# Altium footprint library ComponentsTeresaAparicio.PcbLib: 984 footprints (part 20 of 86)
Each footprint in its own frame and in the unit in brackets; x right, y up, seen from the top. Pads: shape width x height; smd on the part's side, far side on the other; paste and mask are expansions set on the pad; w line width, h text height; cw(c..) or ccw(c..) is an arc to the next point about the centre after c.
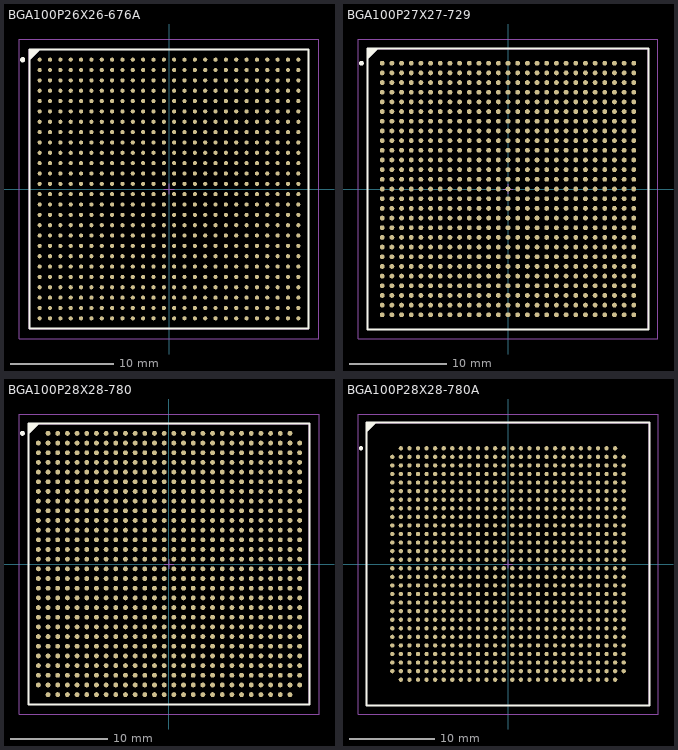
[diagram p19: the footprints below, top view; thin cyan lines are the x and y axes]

## BGA100P26X26-676A [mm] "BGA, 676-Leads, Body 27x27mm, Pitch 1mm"
height 1.6
pads (676):
  round 0.4 smd: A1(-12.5,12.5) A2(-11.5,12.5) A3(-10.5,12.5) A4(-9.5,12.5) A5(-8.5,12.5) A6(-7.5,12.5) A7(-6.5,12.5) A8(-5.5,12.5) A9(-4.5,12.5) A10(-3.5,12.5) A11(-2.5,12.5) A12(-1.5,12.5) A13(-0.5,12.5) A14(0.5,12.5) A15(1.5,12.5) A16(2.5,12.5) A17(3.5,12.5) A18(4.5,12.5) A19(5.5,12.5) A20(6.5,12.5) A21(7.5,12.5) A22(8.5,12.5) A23(9.5,12.5) A24(10.5,12.5) A25(11.5,12.5) A26(12.5,12.5) AA1(-12.5,-7.5) AA2(-11.5,-7.5) AA3(-10.5,-7.5) AA4(-9.5,-7.5) AA5(-8.5,-7.5) AA6(-7.5,-7.5) AA7(-6.5,-7.5) AA8(-5.5,-7.5) AA9(-4.5,-7.5) AA10(-3.5,-7.5) AA11(-2.5,-7.5) AA12(-1.5,-7.5) AA13(-0.5,-7.5) AA14(0.5,-7.5) AA15(1.5,-7.5) AA16(2.5,-7.5) AA17(3.5,-7.5) AA18(4.5,-7.5) AA19(5.5,-7.5) AA20(6.5,-7.5) AA21(7.5,-7.5) AA22(8.5,-7.5) AA23(9.5,-7.5) AA24(10.5,-7.5) AA25(11.5,-7.5) AA26(12.5,-7.5) AB1(-12.5,-8.5) AB2(-11.5,-8.5) AB3(-10.5,-8.5) AB4(-9.5,-8.5) AB5(-8.5,-8.5) AB6(-7.5,-8.5) AB7(-6.5,-8.5) AB8(-5.5,-8.5) AB9(-4.5,-8.5) AB10(-3.5,-8.5) AB11(-2.5,-8.5) AB12(-1.5,-8.5) AB13(-0.5,-8.5) AB14(0.5,-8.5) AB15(1.5,-8.5) AB16(2.5,-8.5) AB17(3.5,-8.5) AB18(4.5,-8.5) AB19(5.5,-8.5) AB20(6.5,-8.5) AB21(7.5,-8.5) AB22(8.5,-8.5) AB23(9.5,-8.5) AB24(10.5,-8.5) AB25(11.5,-8.5) AB26(12.5,-8.5) AC1(-12.5,-9.5) AC2(-11.5,-9.5) AC3(-10.5,-9.5) AC4(-9.5,-9.5) AC5(-8.5,-9.5) AC6(-7.5,-9.5) AC7(-6.5,-9.5) AC8(-5.5,-9.5) AC9(-4.5,-9.5) AC10(-3.5,-9.5) AC11(-2.5,-9.5) AC12(-1.5,-9.5) AC13(-0.5,-9.5) AC14(0.5,-9.5) AC15(1.5,-9.5) AC16(2.5,-9.5) AC17(3.5,-9.5) AC18(4.5,-9.5) AC19(5.5,-9.5) AC20(6.5,-9.5) AC21(7.5,-9.5) AC22(8.5,-9.5) AC23(9.5,-9.5) AC24(10.5,-9.5) AC25(11.5,-9.5) AC26(12.5,-9.5) AD1(-12.5,-10.5) AD2(-11.5,-10.5) AD3(-10.5,-10.5) AD4(-9.5,-10.5) AD5(-8.5,-10.5) AD6(-7.5,-10.5) AD7(-6.5,-10.5) AD8(-5.5,-10.5) AD9(-4.5,-10.5) AD10(-3.5,-10.5) AD11(-2.5,-10.5) AD12(-1.5,-10.5) AD13(-0.5,-10.5) AD14(0.5,-10.5) AD15(1.5,-10.5) AD16(2.5,-10.5) AD17(3.5,-10.5) AD18(4.5,-10.5) AD19(5.5,-10.5) AD20(6.5,-10.5) AD21(7.5,-10.5) AD22(8.5,-10.5) AD23(9.5,-10.5) AD24(10.5,-10.5) AD25(11.5,-10.5) AD26(12.5,-10.5) AE1(-12.5,-11.5) AE2(-11.5,-11.5) AE3(-10.5,-11.5) AE4(-9.5,-11.5) AE5(-8.5,-11.5) AE6(-7.5,-11.5) AE7(-6.5,-11.5) AE8(-5.5,-11.5) AE9(-4.5,-11.5) AE10(-3.5,-11.5) AE11(-2.5,-11.5) AE12(-1.5,-11.5) AE13(-0.5,-11.5) AE14(0.5,-11.5) AE15(1.5,-11.5) AE16(2.5,-11.5) AE17(3.5,-11.5) AE18(4.5,-11.5) AE19(5.5,-11.5) AE20(6.5,-11.5) AE21(7.5,-11.5) AE22(8.5,-11.5) AE23(9.5,-11.5) AE24(10.5,-11.5) AE25(11.5,-11.5) AE26(12.5,-11.5) AF1(-12.5,-12.5) AF2(-11.5,-12.5) AF3(-10.5,-12.5) AF4(-9.5,-12.5) AF5(-8.5,-12.5) AF6(-7.5,-12.5) AF7(-6.5,-12.5) AF8(-5.5,-12.5) AF9(-4.5,-12.5) AF10(-3.5,-12.5) AF11(-2.5,-12.5) AF12(-1.5,-12.5) AF13(-0.5,-12.5) AF14(0.5,-12.5) AF15(1.5,-12.5) AF16(2.5,-12.5) AF17(3.5,-12.5) AF18(4.5,-12.5) AF19(5.5,-12.5) AF20(6.5,-12.5) AF21(7.5,-12.5) AF22(8.5,-12.5) AF23(9.5,-12.5) AF24(10.5,-12.5) AF25(11.5,-12.5) AF26(12.5,-12.5) B1(-12.5,11.5) B2(-11.5,11.5) B3(-10.5,11.5) B4(-9.5,11.5) B5(-8.5,11.5) B6(-7.5,11.5) B7(-6.5,11.5) B8(-5.5,11.5) B9(-4.5,11.5) B10(-3.5,11.5) B11(-2.5,11.5) B12(-1.5,11.5) B13(-0.5,11.5) B14(0.5,11.5) B15(1.5,11.5) B16(2.5,11.5) B17(3.5,11.5) B18(4.5,11.5) B19(5.5,11.5) B20(6.5,11.5) B21(7.5,11.5) B22(8.5,11.5) B23(9.5,11.5) B24(10.5,11.5) B25(11.5,11.5) B26(12.5,11.5) C1(-12.5,10.5) C2(-11.5,10.5) C3(-10.5,10.5) C4(-9.5,10.5) C5(-8.5,10.5) C6(-7.5,10.5) C7(-6.5,10.5) C8(-5.5,10.5) C9(-4.5,10.5) C10(-3.5,10.5) C11(-2.5,10.5) C12(-1.5,10.5) C13(-0.5,10.5) C14(0.5,10.5) C15(1.5,10.5) C16(2.5,10.5) C17(3.5,10.5) C18(4.5,10.5) C19(5.5,10.5) C20(6.5,10.5) C21(7.5,10.5) C22(8.5,10.5) C23(9.5,10.5) C24(10.5,10.5) C25(11.5,10.5) C26(12.5,10.5) D1(-12.5,9.5) D2(-11.5,9.5) D3(-10.5,9.5) D4(-9.5,9.5) D5(-8.5,9.5) D6(-7.5,9.5) D7(-6.5,9.5) D8(-5.5,9.5) D9(-4.5,9.5) D10(-3.5,9.5) D11(-2.5,9.5) D12(-1.5,9.5) D13(-0.5,9.5) D14(0.5,9.5) D15(1.5,9.5) D16(2.5,9.5) D17(3.5,9.5) D18(4.5,9.5) D19(5.5,9.5) D20(6.5,9.5) D21(7.5,9.5) D22(8.5,9.5) D23(9.5,9.5) D24(10.5,9.5) D25(11.5,9.5) D26(12.5,9.5) E1(-12.5,8.5) E2(-11.5,8.5) E3(-10.5,8.5) E4(-9.5,8.5) E5(-8.5,8.5) E6(-7.5,8.5) E7(-6.5,8.5) E8(-5.5,8.5) E9(-4.5,8.5) E10(-3.5,8.5) E11(-2.5,8.5) E12(-1.5,8.5) E13(-0.5,8.5) E14(0.5,8.5) E15(1.5,8.5) E16(2.5,8.5) E17(3.5,8.5) E18(4.5,8.5) E19(5.5,8.5) E20(6.5,8.5) E21(7.5,8.5) E22(8.5,8.5) E23(9.5,8.5) E24(10.5,8.5) E25(11.5,8.5) E26(12.5,8.5) F1(-12.5,7.5) F2(-11.5,7.5) F3(-10.5,7.5) F4(-9.5,7.5) F5(-8.5,7.5) F6(-7.5,7.5) F7(-6.5,7.5) F8(-5.5,7.5) F9(-4.5,7.5) F10(-3.5,7.5) F11(-2.5,7.5) F12(-1.5,7.5) F13(-0.5,7.5) F14(0.5,7.5) F15(1.5,7.5) F16(2.5,7.5) F17(3.5,7.5) F18(4.5,7.5) F19(5.5,7.5) F20(6.5,7.5) F21(7.5,7.5) F22(8.5,7.5) F23(9.5,7.5) F24(10.5,7.5) F25(11.5,7.5) F26(12.5,7.5) G1(-12.5,6.5) G2(-11.5,6.5) G3(-10.5,6.5) G4(-9.5,6.5) G5(-8.5,6.5) G6(-7.5,6.5) G7(-6.5,6.5) G8(-5.5,6.5) G9(-4.5,6.5) G10(-3.5,6.5) G11(-2.5,6.5) G12(-1.5,6.5) G13(-0.5,6.5) G14(0.5,6.5) G15(1.5,6.5) G16(2.5,6.5) G17(3.5,6.5) G18(4.5,6.5) G19(5.5,6.5) G20(6.5,6.5) G21(7.5,6.5) G22(8.5,6.5) G23(9.5,6.5) G24(10.5,6.5) G25(11.5,6.5) G26(12.5,6.5) H1(-12.5,5.5) H2(-11.5,5.5) H3(-10.5,5.5) H4(-9.5,5.5) H5(-8.5,5.5) H6(-7.5,5.5) H7(-6.5,5.5) H8(-5.5,5.5) H9(-4.5,5.5) H10(-3.5,5.5) H11(-2.5,5.5) H12(-1.5,5.5) H13(-0.5,5.5) H14(0.5,5.5) H15(1.5,5.5) H16(2.5,5.5) H17(3.5,5.5) H18(4.5,5.5) H19(5.5,5.5) H20(6.5,5.5) H21(7.5,5.5) H22(8.5,5.5) H23(9.5,5.5) H24(10.5,5.5) H25(11.5,5.5) H26(12.5,5.5) J1(-12.5,4.5) J2(-11.5,4.5) J3(-10.5,4.5) J4(-9.5,4.5) J5(-8.5,4.5) J6(-7.5,4.5) J7(-6.5,4.5) J8(-5.5,4.5) J9(-4.5,4.5) J10(-3.5,4.5) J11(-2.5,4.5) J12(-1.5,4.5) J13(-0.5,4.5) J14(0.5,4.5) J15(1.5,4.5) J16(2.5,4.5) J17(3.5,4.5) J18(4.5,4.5) J19(5.5,4.5) J20(6.5,4.5) J21(7.5,4.5) J22(8.5,4.5) J23(9.5,4.5) J24(10.5,4.5) J25(11.5,4.5) J26(12.5,4.5) K1(-12.5,3.5) K2(-11.5,3.5) K3(-10.5,3.5) K4(-9.5,3.5) K5(-8.5,3.5) K6(-7.5,3.5) K7(-6.5,3.5) K8(-5.5,3.5) K9(-4.5,3.5) K10(-3.5,3.5) K11(-2.5,3.5) K12(-1.5,3.5) K13(-0.5,3.5) K14(0.5,3.5) K15(1.5,3.5) K16(2.5,3.5) K17(3.5,3.5) K18(4.5,3.5) K19(5.5,3.5) K20(6.5,3.5) K21(7.5,3.5) K22(8.5,3.5) K23(9.5,3.5) K24(10.5,3.5) K25(11.5,3.5) K26(12.5,3.5) L1(-12.5,2.5) L2(-11.5,2.5) L3(-10.5,2.5) L4(-9.5,2.5) L5(-8.5,2.5) L6(-7.5,2.5) L7(-6.5,2.5) L8(-5.5,2.5) L9(-4.5,2.5) L10(-3.5,2.5) L11(-2.5,2.5) L12(-1.5,2.5) L13(-0.5,2.5) L14(0.5,2.5) L15(1.5,2.5) L16(2.5,2.5) L17(3.5,2.5) L18(4.5,2.5) L19(5.5,2.5) L20(6.5,2.5) L21(7.5,2.5) L22(8.5,2.5) L23(9.5,2.5) L24(10.5,2.5) L25(11.5,2.5) L26(12.5,2.5) M1(-12.5,1.5) M2(-11.5,1.5) M3(-10.5,1.5) M4(-9.5,1.5) M5(-8.5,1.5) M6(-7.5,1.5) M7(-6.5,1.5) M8(-5.5,1.5) M9(-4.5,1.5) M10(-3.5,1.5) M11(-2.5,1.5) M12(-1.5,1.5) M13(-0.5,1.5) M14(0.5,1.5) M15(1.5,1.5) M16(2.5,1.5) M17(3.5,1.5) M18(4.5,1.5) M19(5.5,1.5) M20(6.5,1.5) M21(7.5,1.5) M22(8.5,1.5) M23(9.5,1.5) M24(10.5,1.5) M25(11.5,1.5) M26(12.5,1.5) N1(-12.5,0.5) N2(-11.5,0.5) N3(-10.5,0.5) N4(-9.5,0.5) N5(-8.5,0.5) N6(-7.5,0.5) N7(-6.5,0.5) N8(-5.5,0.5) N9(-4.5,0.5) N10(-3.5,0.5) N11(-2.5,0.5) N12(-1.5,0.5) N13(-0.5,0.5) N14(0.5,0.5) N15(1.5,0.5) N16(2.5,0.5) N17(3.5,0.5) N18(4.5,0.5) N19(5.5,0.5) N20(6.5,0.5) N21(7.5,0.5) N22(8.5,0.5) N23(9.5,0.5) N24(10.5,0.5) N25(11.5,0.5) N26(12.5,0.5) P1(-12.5,-0.5) P2(-11.5,-0.5) P3(-10.5,-0.5) P4(-9.5,-0.5) P5(-8.5,-0.5) P6(-7.5,-0.5) P7(-6.5,-0.5) P8(-5.5,-0.5) P9(-4.5,-0.5) P10(-3.5,-0.5) P11(-2.5,-0.5) P12(-1.5,-0.5) P13(-0.5,-0.5) P14(0.5,-0.5) P15(1.5,-0.5) P16(2.5,-0.5) P17(3.5,-0.5) P18(4.5,-0.5) P19(5.5,-0.5) P20(6.5,-0.5) P21(7.5,-0.5) P22(8.5,-0.5) P23(9.5,-0.5) P24(10.5,-0.5) P25(11.5,-0.5) P26(12.5,-0.5) R1(-12.5,-1.5) R2(-11.5,-1.5) R3(-10.5,-1.5) R4(-9.5,-1.5) R5(-8.5,-1.5) R6(-7.5,-1.5) R7(-6.5,-1.5) R8(-5.5,-1.5) R9(-4.5,-1.5) R10(-3.5,-1.5) R11(-2.5,-1.5) R12(-1.5,-1.5) R13(-0.5,-1.5) R14(0.5,-1.5) R15(1.5,-1.5) R16(2.5,-1.5) R17(3.5,-1.5) R18(4.5,-1.5) R19(5.5,-1.5) R20(6.5,-1.5) R21(7.5,-1.5) R22(8.5,-1.5) R23(9.5,-1.5) R24(10.5,-1.5) R25(11.5,-1.5) R26(12.5,-1.5) T1(-12.5,-2.5) T2(-11.5,-2.5) T3(-10.5,-2.5) T4(-9.5,-2.5) T5(-8.5,-2.5) T6(-7.5,-2.5) T7(-6.5,-2.5) T8(-5.5,-2.5) T9(-4.5,-2.5) T10(-3.5,-2.5) T11(-2.5,-2.5) T12(-1.5,-2.5) T13(-0.5,-2.5) T14(0.5,-2.5) T15(1.5,-2.5) T16(2.5,-2.5) T17(3.5,-2.5) T18(4.5,-2.5) T19(5.5,-2.5) T20(6.5,-2.5) T21(7.5,-2.5) T22(8.5,-2.5) T23(9.5,-2.5) T24(10.5,-2.5) T25(11.5,-2.5) T26(12.5,-2.5) U1(-12.5,-3.5) U2(-11.5,-3.5) U3(-10.5,-3.5) U4(-9.5,-3.5) U5(-8.5,-3.5) U6(-7.5,-3.5) U7(-6.5,-3.5) U8(-5.5,-3.5) U9(-4.5,-3.5) U10(-3.5,-3.5) U11(-2.5,-3.5) U12(-1.5,-3.5) U13(-0.5,-3.5) U14(0.5,-3.5) U15(1.5,-3.5) U16(2.5,-3.5) U17(3.5,-3.5) U18(4.5,-3.5) U19(5.5,-3.5) U20(6.5,-3.5) U21(7.5,-3.5) U22(8.5,-3.5) U23(9.5,-3.5) U24(10.5,-3.5) U25(11.5,-3.5) U26(12.5,-3.5) V1(-12.5,-4.5) V2(-11.5,-4.5) V3(-10.5,-4.5) V4(-9.5,-4.5) V5(-8.5,-4.5) V6(-7.5,-4.5) V7(-6.5,-4.5) V8(-5.5,-4.5) V9(-4.5,-4.5) V10(-3.5,-4.5) V11(-2.5,-4.5) V12(-1.5,-4.5) V13(-0.5,-4.5) V14(0.5,-4.5) V15(1.5,-4.5) V16(2.5,-4.5) V17(3.5,-4.5) V18(4.5,-4.5) V19(5.5,-4.5) V20(6.5,-4.5) V21(7.5,-4.5) V22(8.5,-4.5) V23(9.5,-4.5) V24(10.5,-4.5) V25(11.5,-4.5) V26(12.5,-4.5) W1(-12.5,-5.5) W2(-11.5,-5.5) W3(-10.5,-5.5) W4(-9.5,-5.5) W5(-8.5,-5.5) W6(-7.5,-5.5) W7(-6.5,-5.5) W8(-5.5,-5.5) W9(-4.5,-5.5) W10(-3.5,-5.5) W11(-2.5,-5.5) W12(-1.5,-5.5) W13(-0.5,-5.5) W14(0.5,-5.5) W15(1.5,-5.5) W16(2.5,-5.5) W17(3.5,-5.5) W18(4.5,-5.5) W19(5.5,-5.5) W20(6.5,-5.5) W21(7.5,-5.5) W22(8.5,-5.5) W23(9.5,-5.5) W24(10.5,-5.5) W25(11.5,-5.5) W26(12.5,-5.5) Y1(-12.5,-6.5) Y2(-11.5,-6.5) Y3(-10.5,-6.5) Y4(-9.5,-6.5) Y5(-8.5,-6.5) Y6(-7.5,-6.5) Y7(-6.5,-6.5) Y8(-5.5,-6.5) Y9(-4.5,-6.5) Y10(-3.5,-6.5) Y11(-2.5,-6.5) Y12(-1.5,-6.5) Y13(-0.5,-6.5) Y14(0.5,-6.5) Y15(1.5,-6.5) Y16(2.5,-6.5) Y17(3.5,-6.5) Y18(4.5,-6.5) Y19(5.5,-6.5) Y20(6.5,-6.5) Y21(7.5,-6.5) Y22(8.5,-6.5) Y23(9.5,-6.5) Y24(10.5,-6.5) Y25(11.5,-6.5) Y26(12.5,-6.5)
Top Overlay:
  circle w0.25: c-14.15,12.5 r0.125
  region: -12.5,13.5 -13.5,12.5 -13.5,13.5
  lines w0.2: -13.5,12.5 -12.5,13.5 ; -13.5,-13.5 -13.5,13.5 13.5,13.5 13.5,-13.5 -13.5,-13.5
Mechanical 13:
  lines w0.1: -13.5,-13.5 -13.5,13.5 13.5,13.5 13.5,-13.5 -13.5,-13.5
Mechanical 15:
  lines w0.1: -0.5,0 0.5,0 ; 0,-0.5 0,0.5 ; -14.5,-14.5 -14.5,14.5 14.5,14.5 14.5,-14.5 -14.5,-14.5
3D body: height 0, standoff 0, extent -13.5,-13.5 13.5,13.5

## BGA100P27X27-729 [mm] "BGA, 729-Leads, Body 29x29mm, Pitch 1mm"
height 3.5
pads (729):
  round 0.5 smd: A1(-13,13) A2(-12,13) A3(-11,13) A4(-10,13) A5(-9,13) A6(-8,13) A7(-7,13) A8(-6,13) A9(-5,13) A10(-4,13) A11(-3,13) A12(-2,13) A13(-1,13) A14(0,13) A15(1,13) A16(2,13) A17(3,13) A18(4,13) A19(5,13) A20(6,13) A21(7,13) A22(8,13) A23(9,13) A24(10,13) A25(11,13) A26(12,13) A27(13,13) AA1(-13,-7) AA2(-12,-7) AA3(-11,-7) AA4(-10,-7) AA5(-9,-7) AA6(-8,-7) AA7(-7,-7) AA8(-6,-7) AA9(-5,-7) AA10(-4,-7) AA11(-3,-7) AA12(-2,-7) AA13(-1,-7) AA14(0,-7) AA15(1,-7) AA16(2,-7) AA17(3,-7) AA18(4,-7) AA19(5,-7) AA20(6,-7) AA21(7,-7) AA22(8,-7) AA23(9,-7) AA24(10,-7) AA25(11,-7) AA26(12,-7) AA27(13,-7) AB1(-13,-8) AB2(-12,-8) AB3(-11,-8) AB4(-10,-8) AB5(-9,-8) AB6(-8,-8) AB7(-7,-8) AB8(-6,-8) AB9(-5,-8) AB10(-4,-8) AB11(-3,-8) AB12(-2,-8) AB13(-1,-8) AB14(0,-8) AB15(1,-8) AB16(2,-8) AB17(3,-8) AB18(4,-8) AB19(5,-8) AB20(6,-8) AB21(7,-8) AB22(8,-8) AB23(9,-8) AB24(10,-8) AB25(11,-8) AB26(12,-8) AB27(13,-8) AC1(-13,-9) AC2(-12,-9) AC3(-11,-9) AC4(-10,-9) AC5(-9,-9) AC6(-8,-9) AC7(-7,-9) AC8(-6,-9) AC9(-5,-9) AC10(-4,-9) AC11(-3,-9) AC12(-2,-9) AC13(-1,-9) AC14(0,-9) AC15(1,-9) AC16(2,-9) AC17(3,-9) AC18(4,-9) AC19(5,-9) AC20(6,-9) AC21(7,-9) AC22(8,-9) AC23(9,-9) AC24(10,-9) AC25(11,-9) AC26(12,-9) AC27(13,-9) AD1(-13,-10) AD2(-12,-10) AD3(-11,-10) AD4(-10,-10) AD5(-9,-10) AD6(-8,-10) AD7(-7,-10) AD8(-6,-10) AD9(-5,-10) AD10(-4,-10) AD11(-3,-10) AD12(-2,-10) AD13(-1,-10) AD14(0,-10) AD15(1,-10) AD16(2,-10) AD17(3,-10) AD18(4,-10) AD19(5,-10) AD20(6,-10) AD21(7,-10) AD22(8,-10) AD23(9,-10) AD24(10,-10) AD25(11,-10) AD26(12,-10) AD27(13,-10) AE1(-13,-11) AE2(-12,-11) AE3(-11,-11) AE4(-10,-11) AE5(-9,-11) AE6(-8,-11) AE7(-7,-11) AE8(-6,-11) AE9(-5,-11) AE10(-4,-11) AE11(-3,-11) AE12(-2,-11) AE13(-1,-11) AE14(0,-11) AE15(1,-11) AE16(2,-11) AE17(3,-11) AE18(4,-11) AE19(5,-11) AE20(6,-11) AE21(7,-11) AE22(8,-11) AE23(9,-11) AE24(10,-11) AE25(11,-11) AE26(12,-11) AE27(13,-11) AF1(-13,-12) AF2(-12,-12) AF3(-11,-12) AF4(-10,-12) AF5(-9,-12) AF6(-8,-12) AF7(-7,-12) AF8(-6,-12) AF9(-5,-12) AF10(-4,-12) AF11(-3,-12) AF12(-2,-12) AF13(-1,-12) AF14(0,-12) AF15(1,-12) AF16(2,-12) AF17(3,-12) AF18(4,-12) AF19(5,-12) AF20(6,-12) AF21(7,-12) AF22(8,-12) AF23(9,-12) AF24(10,-12) AF25(11,-12) AF26(12,-12) AF27(13,-12) AG1(-13,-13) AG2(-12,-13) AG3(-11,-13) AG4(-10,-13) AG5(-9,-13) AG6(-8,-13) AG7(-7,-13) AG8(-6,-13) AG9(-5,-13) AG10(-4,-13) AG11(-3,-13) AG12(-2,-13) AG13(-1,-13) AG14(0,-13) AG15(1,-13) AG16(2,-13) AG17(3,-13) AG18(4,-13) AG19(5,-13) AG20(6,-13) AG21(7,-13) AG22(8,-13) AG23(9,-13) AG24(10,-13) AG25(11,-13) AG26(12,-13) AG27(13,-13) B1(-13,12) B2(-12,12) B3(-11,12) B4(-10,12) B5(-9,12) B6(-8,12) B7(-7,12) B8(-6,12) B9(-5,12) B10(-4,12) B11(-3,12) B12(-2,12) B13(-1,12) B14(0,12) B15(1,12) B16(2,12) B17(3,12) B18(4,12) B19(5,12) B20(6,12) B21(7,12) B22(8,12) B23(9,12) B24(10,12) B25(11,12) B26(12,12) B27(13,12) C1(-13,11) C2(-12,11) C3(-11,11) C4(-10,11) C5(-9,11) C6(-8,11) C7(-7,11) C8(-6,11) C9(-5,11) C10(-4,11) C11(-3,11) C12(-2,11) C13(-1,11) C14(0,11) C15(1,11) C16(2,11) C17(3,11) C18(4,11) C19(5,11) C20(6,11) C21(7,11) C22(8,11) C23(9,11) C24(10,11) C25(11,11) C26(12,11) C27(13,11) D1(-13,10) D2(-12,10) D3(-11,10) D4(-10,10) D5(-9,10) D6(-8,10) D7(-7,10) D8(-6,10) D9(-5,10) D10(-4,10) D11(-3,10) D12(-2,10) D13(-1,10) D14(0,10) D15(1,10) D16(2,10) D17(3,10) D18(4,10) D19(5,10) D20(6,10) D21(7,10) D22(8,10) D23(9,10) D24(10,10) D25(11,10) D26(12,10) D27(13,10) E1(-13,9) E2(-12,9) E3(-11,9) E4(-10,9) E5(-9,9) E6(-8,9) E7(-7,9) E8(-6,9) E9(-5,9) E10(-4,9) E11(-3,9) E12(-2,9) E13(-1,9) E14(0,9) E15(1,9) E16(2,9) E17(3,9) E18(4,9) E19(5,9) E20(6,9) E21(7,9) E22(8,9) E23(9,9) E24(10,9) E25(11,9) E26(12,9) E27(13,9) F1(-13,8) F2(-12,8) F3(-11,8) F4(-10,8) F5(-9,8) F6(-8,8) F7(-7,8) F8(-6,8) F9(-5,8) F10(-4,8) F11(-3,8) F12(-2,8) F13(-1,8) F14(0,8) F15(1,8) F16(2,8) F17(3,8) F18(4,8) F19(5,8) F20(6,8) F21(7,8) F22(8,8) F23(9,8) F24(10,8) F25(11,8) F26(12,8) F27(13,8) G1(-13,7) G2(-12,7) G3(-11,7) G4(-10,7) G5(-9,7) G6(-8,7) G7(-7,7) G8(-6,7) G9(-5,7) G10(-4,7) G11(-3,7) G12(-2,7) G13(-1,7) G14(0,7) G15(1,7) G16(2,7) G17(3,7) G18(4,7) G19(5,7) G20(6,7) G21(7,7) G22(8,7) G23(9,7) G24(10,7) G25(11,7) G26(12,7) G27(13,7) H1(-13,6) H2(-12,6) H3(-11,6) H4(-10,6) H5(-9,6) H6(-8,6) H7(-7,6) H8(-6,6) H9(-5,6) H10(-4,6) H11(-3,6) H12(-2,6) H13(-1,6) H14(0,6) H15(1,6) H16(2,6) H17(3,6) H18(4,6) H19(5,6) H20(6,6) H21(7,6) H22(8,6) H23(9,6) H24(10,6) H25(11,6) H26(12,6) H27(13,6) J1(-13,5) J2(-12,5) J3(-11,5) J4(-10,5) J5(-9,5) J6(-8,5) J7(-7,5) J8(-6,5) J9(-5,5) J10(-4,5) J11(-3,5) J12(-2,5) J13(-1,5) J14(0,5) J15(1,5) J16(2,5) J17(3,5) J18(4,5) J19(5,5) J20(6,5) J21(7,5) J22(8,5) J23(9,5) J24(10,5) J25(11,5) J26(12,5) J27(13,5) K1(-13,4) K2(-12,4) K3(-11,4) K4(-10,4) K5(-9,4) K6(-8,4) K7(-7,4) K8(-6,4) K9(-5,4) K10(-4,4) K11(-3,4) K12(-2,4) K13(-1,4) K14(0,4) K15(1,4) K16(2,4) K17(3,4) K18(4,4) K19(5,4) K20(6,4) K21(7,4) K22(8,4) K23(9,4) K24(10,4) K25(11,4) K26(12,4) K27(13,4) L1(-13,3) L2(-12,3) L3(-11,3) L4(-10,3) L5(-9,3) L6(-8,3) L7(-7,3) L8(-6,3) L9(-5,3) L10(-4,3) L11(-3,3) L12(-2,3) L13(-1,3) L14(0,3) L15(1,3) L16(2,3) L17(3,3) L18(4,3) L19(5,3) L20(6,3) L21(7,3) L22(8,3) L23(9,3) L24(10,3) L25(11,3) L26(12,3) L27(13,3) M1(-13,2) M2(-12,2) M3(-11,2) M4(-10,2) M5(-9,2) M6(-8,2) M7(-7,2) M8(-6,2) M9(-5,2) M10(-4,2) M11(-3,2) M12(-2,2) M13(-1,2) M14(0,2) M15(1,2) M16(2,2) M17(3,2) M18(4,2) M19(5,2) M20(6,2) M21(7,2) M22(8,2) M23(9,2) M24(10,2) M25(11,2) M26(12,2) M27(13,2) N1(-13,1) N2(-12,1) N3(-11,1) N4(-10,1) N5(-9,1) N6(-8,1) N7(-7,1) N8(-6,1) N9(-5,1) N10(-4,1) N11(-3,1) N12(-2,1) N13(-1,1) N14(0,1) N15(1,1) N16(2,1) N17(3,1) N18(4,1) N19(5,1) N20(6,1) N21(7,1) N22(8,1) N23(9,1) N24(10,1) N25(11,1) N26(12,1) N27(13,1) P1(-13,0) P2(-12,0) P3(-11,0) P4(-10,0) P5(-9,0) P6(-8,0) P7(-7,0) P8(-6,0) P9(-5,0) P10(-4,0) P11(-3,0) P12(-2,0) P13(-1,0) P14(0,0) P15(1,0) P16(2,0) P17(3,0) P18(4,0) P19(5,0) P20(6,0) P21(7,0) P22(8,0) P23(9,0) P24(10,0) P25(11,0) P26(12,0) P27(13,0) R1(-13,-1) R2(-12,-1) R3(-11,-1) R4(-10,-1) R5(-9,-1) R6(-8,-1) R7(-7,-1) R8(-6,-1) R9(-5,-1) R10(-4,-1) R11(-3,-1) R12(-2,-1) R13(-1,-1) R14(0,-1) R15(1,-1) R16(2,-1) R17(3,-1) R18(4,-1) R19(5,-1) R20(6,-1) R21(7,-1) R22(8,-1) R23(9,-1) R24(10,-1) R25(11,-1) R26(12,-1) R27(13,-1) T1(-13,-2) T2(-12,-2) T3(-11,-2) T4(-10,-2) T5(-9,-2) T6(-8,-2) T7(-7,-2) T8(-6,-2) T9(-5,-2) T10(-4,-2) T11(-3,-2) T12(-2,-2) T13(-1,-2) T14(0,-2) T15(1,-2) T16(2,-2) T17(3,-2) T18(4,-2) T19(5,-2) T20(6,-2) T21(7,-2) T22(8,-2) T23(9,-2) T24(10,-2) T25(11,-2) T26(12,-2) T27(13,-2) U1(-13,-3) U2(-12,-3) U3(-11,-3) U4(-10,-3) U5(-9,-3) U6(-8,-3) U7(-7,-3) U8(-6,-3) U9(-5,-3) U10(-4,-3) U11(-3,-3) U12(-2,-3) U13(-1,-3) U14(0,-3) U15(1,-3) U16(2,-3) U17(3,-3) U18(4,-3) U19(5,-3) U20(6,-3) U21(7,-3) U22(8,-3) U23(9,-3) U24(10,-3) U25(11,-3) U26(12,-3) U27(13,-3) V1(-13,-4) V2(-12,-4) V3(-11,-4) V4(-10,-4) V5(-9,-4) V6(-8,-4) V7(-7,-4) V8(-6,-4) V9(-5,-4) V10(-4,-4) V11(-3,-4) V12(-2,-4) V13(-1,-4) V14(0,-4) V15(1,-4) V16(2,-4) V17(3,-4) V18(4,-4) V19(5,-4) V20(6,-4) V21(7,-4) V22(8,-4) V23(9,-4) V24(10,-4) V25(11,-4) V26(12,-4) V27(13,-4) W1(-13,-5) W2(-12,-5) W3(-11,-5) W4(-10,-5) W5(-9,-5) W6(-8,-5) W7(-7,-5) W8(-6,-5) W9(-5,-5) W10(-4,-5) W11(-3,-5) W12(-2,-5) W13(-1,-5) W14(0,-5) W15(1,-5) W16(2,-5) W17(3,-5) W18(4,-5) W19(5,-5) W20(6,-5) W21(7,-5) W22(8,-5) W23(9,-5) W24(10,-5) W25(11,-5) W26(12,-5) W27(13,-5) Y1(-13,-6) Y2(-12,-6) Y3(-11,-6) Y4(-10,-6) Y5(-9,-6) Y6(-8,-6) Y7(-7,-6) Y8(-6,-6) Y9(-5,-6) Y10(-4,-6) Y11(-3,-6) Y12(-2,-6) Y13(-1,-6) Y14(0,-6) Y15(1,-6) Y16(2,-6) Y17(3,-6) Y18(4,-6) Y19(5,-6) Y20(6,-6) Y21(7,-6) Y22(8,-6) Y23(9,-6) Y24(10,-6) Y25(11,-6) Y26(12,-6) Y27(13,-6)
Top Overlay:
  circle w0.25: c-15.15,13 r0.125
  region: -13.5,14.5 -14.5,13.5 -14.5,14.5
  lines w0.2: -14.5,13.5 -13.5,14.5 ; -14.5,-14.5 -14.5,14.5 14.5,14.5 14.5,-14.5 -14.5,-14.5
Mechanical 13:
  lines w0.1: -14.5,-14.5 -14.5,14.5 14.5,14.5 14.5,-14.5 -14.5,-14.5
Mechanical 15:
  lines w0.1: -0.5,0 0.5,0 ; 0,-0.5 0,0.5 ; -15.5,-15.5 -15.5,15.5 15.5,15.5 15.5,-15.5 -15.5,-15.5
3D body: height 0, standoff 0, extent -14.5,-14.5 14.5,14.5

## BGA100P28X28-780 [mm] "BGA, 780-Leads, Body 29x29mm, Pitch 1mm"
height 3.5
pads (780):
  round 0.5 smd: A2(-12.5,13.5) A3(-11.5,13.5) A4(-10.5,13.5) A5(-9.5,13.5) A6(-8.5,13.5) A7(-7.5,13.5) A8(-6.5,13.5) A9(-5.5,13.5) A10(-4.5,13.5) A11(-3.5,13.5) A12(-2.5,13.5) A13(-1.5,13.5) A14(-0.5,13.5) A15(0.5,13.5) A16(1.5,13.5) A17(2.5,13.5) A18(3.5,13.5) A19(4.5,13.5) A20(5.5,13.5) A21(6.5,13.5) A22(7.5,13.5) A23(8.5,13.5) A24(9.5,13.5) A25(10.5,13.5) A26(11.5,13.5) A27(12.5,13.5) AA1(-13.5,-6.5) AA2(-12.5,-6.5) AA3(-11.5,-6.5) AA4(-10.5,-6.5) AA5(-9.5,-6.5) AA6(-8.5,-6.5) AA7(-7.5,-6.5) AA8(-6.5,-6.5) AA9(-5.5,-6.5) AA10(-4.5,-6.5) AA11(-3.5,-6.5) AA12(-2.5,-6.5) AA13(-1.5,-6.5) AA14(-0.5,-6.5) AA15(0.5,-6.5) AA16(1.5,-6.5) AA17(2.5,-6.5) AA18(3.5,-6.5) AA19(4.5,-6.5) AA20(5.5,-6.5) AA21(6.5,-6.5) AA22(7.5,-6.5) AA23(8.5,-6.5) AA24(9.5,-6.5) AA25(10.5,-6.5) AA26(11.5,-6.5) AA27(12.5,-6.5) AA28(13.5,-6.5) AB1(-13.5,-7.5) AB2(-12.5,-7.5) AB3(-11.5,-7.5) AB4(-10.5,-7.5) AB5(-9.5,-7.5) AB6(-8.5,-7.5) AB7(-7.5,-7.5) AB8(-6.5,-7.5) AB9(-5.5,-7.5) AB10(-4.5,-7.5) AB11(-3.5,-7.5) AB12(-2.5,-7.5) AB13(-1.5,-7.5) AB14(-0.5,-7.5) AB15(0.5,-7.5) AB16(1.5,-7.5) AB17(2.5,-7.5) AB18(3.5,-7.5) AB19(4.5,-7.5) AB20(5.5,-7.5) AB21(6.5,-7.5) AB22(7.5,-7.5) AB23(8.5,-7.5) AB24(9.5,-7.5) AB25(10.5,-7.5) AB26(11.5,-7.5) AB27(12.5,-7.5) AB28(13.5,-7.5) AC1(-13.5,-8.5) AC2(-12.5,-8.5) AC3(-11.5,-8.5) AC4(-10.5,-8.5) AC5(-9.5,-8.5) AC6(-8.5,-8.5) AC7(-7.5,-8.5) AC8(-6.5,-8.5) AC9(-5.5,-8.5) AC10(-4.5,-8.5) AC11(-3.5,-8.5) AC12(-2.5,-8.5) AC13(-1.5,-8.5) AC14(-0.5,-8.5) AC15(0.5,-8.5) AC16(1.5,-8.5) AC17(2.5,-8.5) AC18(3.5,-8.5) AC19(4.5,-8.5) AC20(5.5,-8.5) AC21(6.5,-8.5) AC22(7.5,-8.5) AC23(8.5,-8.5) AC24(9.5,-8.5) AC25(10.5,-8.5) AC26(11.5,-8.5) AC27(12.5,-8.5) AC28(13.5,-8.5) AD1(-13.5,-9.5) AD2(-12.5,-9.5) AD3(-11.5,-9.5) AD4(-10.5,-9.5) AD5(-9.5,-9.5) AD6(-8.5,-9.5) AD7(-7.5,-9.5) AD8(-6.5,-9.5) AD9(-5.5,-9.5) AD10(-4.5,-9.5) AD11(-3.5,-9.5) AD12(-2.5,-9.5) AD13(-1.5,-9.5) AD14(-0.5,-9.5) AD15(0.5,-9.5) AD16(1.5,-9.5) AD17(2.5,-9.5) AD18(3.5,-9.5) AD19(4.5,-9.5) AD20(5.5,-9.5) AD21(6.5,-9.5) AD22(7.5,-9.5) AD23(8.5,-9.5) AD24(9.5,-9.5) AD25(10.5,-9.5) AD26(11.5,-9.5) AD27(12.5,-9.5) AD28(13.5,-9.5) AE1(-13.5,-10.5) AE2(-12.5,-10.5) AE3(-11.5,-10.5) AE4(-10.5,-10.5) AE5(-9.5,-10.5) AE6(-8.5,-10.5) AE7(-7.5,-10.5) AE8(-6.5,-10.5) AE9(-5.5,-10.5) AE10(-4.5,-10.5) AE11(-3.5,-10.5) AE12(-2.5,-10.5) AE13(-1.5,-10.5) AE14(-0.5,-10.5) AE15(0.5,-10.5) AE16(1.5,-10.5) AE17(2.5,-10.5) AE18(3.5,-10.5) AE19(4.5,-10.5) AE20(5.5,-10.5) AE21(6.5,-10.5) AE22(7.5,-10.5) AE23(8.5,-10.5) AE24(9.5,-10.5) AE25(10.5,-10.5) AE26(11.5,-10.5) AE27(12.5,-10.5) AE28(13.5,-10.5) AF1(-13.5,-11.5) AF2(-12.5,-11.5) AF3(-11.5,-11.5) AF4(-10.5,-11.5) AF5(-9.5,-11.5) AF6(-8.5,-11.5) AF7(-7.5,-11.5) AF8(-6.5,-11.5) AF9(-5.5,-11.5) AF10(-4.5,-11.5) AF11(-3.5,-11.5) AF12(-2.5,-11.5) AF13(-1.5,-11.5) AF14(-0.5,-11.5) AF15(0.5,-11.5) AF16(1.5,-11.5) AF17(2.5,-11.5) AF18(3.5,-11.5) AF19(4.5,-11.5) AF20(5.5,-11.5) AF21(6.5,-11.5) AF22(7.5,-11.5) AF23(8.5,-11.5) AF24(9.5,-11.5) AF25(10.5,-11.5) AF26(11.5,-11.5) AF27(12.5,-11.5) AF28(13.5,-11.5) AG1(-13.5,-12.5) AG2(-12.5,-12.5) AG3(-11.5,-12.5) AG4(-10.5,-12.5) AG5(-9.5,-12.5) AG6(-8.5,-12.5) AG7(-7.5,-12.5) AG8(-6.5,-12.5) AG9(-5.5,-12.5) AG10(-4.5,-12.5) AG11(-3.5,-12.5) AG12(-2.5,-12.5) AG13(-1.5,-12.5) AG14(-0.5,-12.5) AG15(0.5,-12.5) AG16(1.5,-12.5) AG17(2.5,-12.5) AG18(3.5,-12.5) AG19(4.5,-12.5) AG20(5.5,-12.5) AG21(6.5,-12.5) AG22(7.5,-12.5) AG23(8.5,-12.5) AG24(9.5,-12.5) AG25(10.5,-12.5) AG26(11.5,-12.5) AG27(12.5,-12.5) AG28(13.5,-12.5) AH2(-12.5,-13.5) AH3(-11.5,-13.5) AH4(-10.5,-13.5) AH5(-9.5,-13.5) AH6(-8.5,-13.5) AH7(-7.5,-13.5) AH8(-6.5,-13.5) AH9(-5.5,-13.5) AH10(-4.5,-13.5) AH11(-3.5,-13.5) AH12(-2.5,-13.5) AH13(-1.5,-13.5) AH14(-0.5,-13.5) AH15(0.5,-13.5) AH16(1.5,-13.5) AH17(2.5,-13.5) AH18(3.5,-13.5) AH19(4.5,-13.5) AH20(5.5,-13.5) AH21(6.5,-13.5) AH22(7.5,-13.5) AH23(8.5,-13.5) AH24(9.5,-13.5) AH25(10.5,-13.5) AH26(11.5,-13.5) AH27(12.5,-13.5) B1(-13.5,12.5) B2(-12.5,12.5) B3(-11.5,12.5) B4(-10.5,12.5) B5(-9.5,12.5) B6(-8.5,12.5) B7(-7.5,12.5) B8(-6.5,12.5) B9(-5.5,12.5) B10(-4.5,12.5) B11(-3.5,12.5) B12(-2.5,12.5) B13(-1.5,12.5) B14(-0.5,12.5) B15(0.5,12.5) B16(1.5,12.5) B17(2.5,12.5) B18(3.5,12.5) B19(4.5,12.5) B20(5.5,12.5) B21(6.5,12.5) B22(7.5,12.5) B23(8.5,12.5) B24(9.5,12.5) B25(10.5,12.5) B26(11.5,12.5) B27(12.5,12.5) B28(13.5,12.5) C1(-13.5,11.5) C2(-12.5,11.5) C3(-11.5,11.5) C4(-10.5,11.5) C5(-9.5,11.5) C6(-8.5,11.5) C7(-7.5,11.5) C8(-6.5,11.5) C9(-5.5,11.5) C10(-4.5,11.5) C11(-3.5,11.5) C12(-2.5,11.5) C13(-1.5,11.5) C14(-0.5,11.5) C15(0.5,11.5) C16(1.5,11.5) C17(2.5,11.5) C18(3.5,11.5) C19(4.5,11.5) C20(5.5,11.5) C21(6.5,11.5) C22(7.5,11.5) C23(8.5,11.5) C24(9.5,11.5) C25(10.5,11.5) C26(11.5,11.5) C27(12.5,11.5) C28(13.5,11.5) D1(-13.5,10.5) D2(-12.5,10.5) D3(-11.5,10.5) D4(-10.5,10.5) D5(-9.5,10.5) D6(-8.5,10.5) D7(-7.5,10.5) D8(-6.5,10.5) D9(-5.5,10.5) D10(-4.5,10.5) D11(-3.5,10.5) D12(-2.5,10.5) D13(-1.5,10.5) D14(-0.5,10.5) D15(0.5,10.5) D16(1.5,10.5) D17(2.5,10.5) D18(3.5,10.5) D19(4.5,10.5) D20(5.5,10.5) D21(6.5,10.5) D22(7.5,10.5) D23(8.5,10.5) D24(9.5,10.5) D25(10.5,10.5) D26(11.5,10.5) D27(12.5,10.5) D28(13.5,10.5) E1(-13.5,9.5) E2(-12.5,9.5) E3(-11.5,9.5) E4(-10.5,9.5) E5(-9.5,9.5) E6(-8.5,9.5) E7(-7.5,9.5) E8(-6.5,9.5) E9(-5.5,9.5) E10(-4.5,9.5) E11(-3.5,9.5) E12(-2.5,9.5) E13(-1.5,9.5) E14(-0.5,9.5) E15(0.5,9.5) E16(1.5,9.5) E17(2.5,9.5) E18(3.5,9.5) E19(4.5,9.5) E20(5.5,9.5) E21(6.5,9.5) E22(7.5,9.5) E23(8.5,9.5) E24(9.5,9.5) E25(10.5,9.5) E26(11.5,9.5) E27(12.5,9.5) E28(13.5,9.5) F1(-13.5,8.5) F2(-12.5,8.5) F3(-11.5,8.5) F4(-10.5,8.5) F5(-9.5,8.5) F6(-8.5,8.5) F7(-7.5,8.5) F8(-6.5,8.5) F9(-5.5,8.5) F10(-4.5,8.5) F11(-3.5,8.5) F12(-2.5,8.5) F13(-1.5,8.5) F14(-0.5,8.5) F15(0.5,8.5) F16(1.5,8.5) F17(2.5,8.5) F18(3.5,8.5) F19(4.5,8.5) F20(5.5,8.5) F21(6.5,8.5) F22(7.5,8.5) F23(8.5,8.5) F24(9.5,8.5) F25(10.5,8.5) F26(11.5,8.5) F27(12.5,8.5) F28(13.5,8.5) G1(-13.5,7.5) G2(-12.5,7.5) G3(-11.5,7.5) G4(-10.5,7.5) G5(-9.5,7.5) G6(-8.5,7.5) G7(-7.5,7.5) G8(-6.5,7.5) G9(-5.5,7.5) G10(-4.5,7.5) G11(-3.5,7.5) G12(-2.5,7.5) G13(-1.5,7.5) G14(-0.5,7.5) G15(0.5,7.5) G16(1.5,7.5) G17(2.5,7.5) G18(3.5,7.5) G19(4.5,7.5) G20(5.5,7.5) G21(6.5,7.5) G22(7.5,7.5) G23(8.5,7.5) G24(9.5,7.5) G25(10.5,7.5) G26(11.5,7.5) G27(12.5,7.5) G28(13.5,7.5) H1(-13.5,6.5) H2(-12.5,6.5) H3(-11.5,6.5) H4(-10.5,6.5) H5(-9.5,6.5) H6(-8.5,6.5) H7(-7.5,6.5) H8(-6.5,6.5) H9(-5.5,6.5) H10(-4.5,6.5) H11(-3.5,6.5) H12(-2.5,6.5) H13(-1.5,6.5) H14(-0.5,6.5) H15(0.5,6.5) H16(1.5,6.5) H17(2.5,6.5) H18(3.5,6.5) H19(4.5,6.5) H20(5.5,6.5) H21(6.5,6.5) H22(7.5,6.5) H23(8.5,6.5) H24(9.5,6.5) H25(10.5,6.5) H26(11.5,6.5) H27(12.5,6.5) H28(13.5,6.5) J1(-13.5,5.5) J2(-12.5,5.5) J3(-11.5,5.5) J4(-10.5,5.5) J5(-9.5,5.5) J6(-8.5,5.5) J7(-7.5,5.5) J8(-6.5,5.5) J9(-5.5,5.5) J10(-4.5,5.5) J11(-3.5,5.5) J12(-2.5,5.5) J13(-1.5,5.5) J14(-0.5,5.5) J15(0.5,5.5) J16(1.5,5.5) J17(2.5,5.5) J18(3.5,5.5) J19(4.5,5.5) J20(5.5,5.5) J21(6.5,5.5) J22(7.5,5.5) J23(8.5,5.5) J24(9.5,5.5) J25(10.5,5.5) J26(11.5,5.5) J27(12.5,5.5) J28(13.5,5.5) K1(-13.5,4.5) K2(-12.5,4.5) K3(-11.5,4.5) K4(-10.5,4.5) K5(-9.5,4.5) K6(-8.5,4.5) K7(-7.5,4.5) K8(-6.5,4.5) K9(-5.5,4.5) K10(-4.5,4.5) K11(-3.5,4.5) K12(-2.5,4.5) K13(-1.5,4.5) K14(-0.5,4.5) K15(0.5,4.5) K16(1.5,4.5) K17(2.5,4.5) K18(3.5,4.5) K19(4.5,4.5) K20(5.5,4.5) K21(6.5,4.5) K22(7.5,4.5) K23(8.5,4.5) K24(9.5,4.5) K25(10.5,4.5) K26(11.5,4.5) K27(12.5,4.5) K28(13.5,4.5) L1(-13.5,3.5) L2(-12.5,3.5) L3(-11.5,3.5) L4(-10.5,3.5) L5(-9.5,3.5) L6(-8.5,3.5) L7(-7.5,3.5) L8(-6.5,3.5) L9(-5.5,3.5) L10(-4.5,3.5) L11(-3.5,3.5) L12(-2.5,3.5) L13(-1.5,3.5) L14(-0.5,3.5) L15(0.5,3.5) L16(1.5,3.5) L17(2.5,3.5) L18(3.5,3.5) L19(4.5,3.5) L20(5.5,3.5) L21(6.5,3.5) L22(7.5,3.5) L23(8.5,3.5) L24(9.5,3.5) L25(10.5,3.5) L26(11.5,3.5) L27(12.5,3.5) L28(13.5,3.5) M1(-13.5,2.5) M2(-12.5,2.5) M3(-11.5,2.5) M4(-10.5,2.5) M5(-9.5,2.5) M6(-8.5,2.5) M7(-7.5,2.5) M8(-6.5,2.5) M9(-5.5,2.5) M10(-4.5,2.5) M11(-3.5,2.5) M12(-2.5,2.5) M13(-1.5,2.5) M14(-0.5,2.5) M15(0.5,2.5) M16(1.5,2.5) M17(2.5,2.5) M18(3.5,2.5) M19(4.5,2.5) M20(5.5,2.5) M21(6.5,2.5) M22(7.5,2.5) M23(8.5,2.5) M24(9.5,2.5) M25(10.5,2.5) M26(11.5,2.5) M27(12.5,2.5) M28(13.5,2.5) N1(-13.5,1.5) N2(-12.5,1.5) N3(-11.5,1.5) N4(-10.5,1.5) N5(-9.5,1.5) N6(-8.5,1.5) N7(-7.5,1.5) N8(-6.5,1.5) N9(-5.5,1.5) N10(-4.5,1.5) N11(-3.5,1.5) N12(-2.5,1.5) N13(-1.5,1.5) N14(-0.5,1.5) N15(0.5,1.5) N16(1.5,1.5) N17(2.5,1.5) N18(3.5,1.5) N19(4.5,1.5) N20(5.5,1.5) N21(6.5,1.5) N22(7.5,1.5) N23(8.5,1.5) N24(9.5,1.5) N25(10.5,1.5) N26(11.5,1.5) N27(12.5,1.5) N28(13.5,1.5) P1(-13.5,0.5) P2(-12.5,0.5) P3(-11.5,0.5) P4(-10.5,0.5) P5(-9.5,0.5) P6(-8.5,0.5) P7(-7.5,0.5) P8(-6.5,0.5) P9(-5.5,0.5) P10(-4.5,0.5) P11(-3.5,0.5) P12(-2.5,0.5) P13(-1.5,0.5) P14(-0.5,0.5) P15(0.5,0.5) P16(1.5,0.5) P17(2.5,0.5) P18(3.5,0.5) P19(4.5,0.5) P20(5.5,0.5) P21(6.5,0.5) P22(7.5,0.5) P23(8.5,0.5) P24(9.5,0.5) P25(10.5,0.5) P26(11.5,0.5) P27(12.5,0.5) P28(13.5,0.5) R1(-13.5,-0.5) R2(-12.5,-0.5) R3(-11.5,-0.5) R4(-10.5,-0.5) R5(-9.5,-0.5) R6(-8.5,-0.5) R7(-7.5,-0.5) R8(-6.5,-0.5) R9(-5.5,-0.5) R10(-4.5,-0.5) R11(-3.5,-0.5) R12(-2.5,-0.5) R13(-1.5,-0.5) R14(-0.5,-0.5) R15(0.5,-0.5) R16(1.5,-0.5) R17(2.5,-0.5) R18(3.5,-0.5) R19(4.5,-0.5) R20(5.5,-0.5) R21(6.5,-0.5) R22(7.5,-0.5) R23(8.5,-0.5) R24(9.5,-0.5) R25(10.5,-0.5) R26(11.5,-0.5) R27(12.5,-0.5) R28(13.5,-0.5) T1(-13.5,-1.5) T2(-12.5,-1.5) T3(-11.5,-1.5) T4(-10.5,-1.5) T5(-9.5,-1.5) T6(-8.5,-1.5) T7(-7.5,-1.5) T8(-6.5,-1.5) T9(-5.5,-1.5) T10(-4.5,-1.5) T11(-3.5,-1.5) T12(-2.5,-1.5) T13(-1.5,-1.5) T14(-0.5,-1.5) T15(0.5,-1.5) T16(1.5,-1.5) T17(2.5,-1.5) T18(3.5,-1.5) T19(4.5,-1.5) T20(5.5,-1.5) T21(6.5,-1.5) T22(7.5,-1.5) T23(8.5,-1.5) T24(9.5,-1.5) T25(10.5,-1.5) T26(11.5,-1.5) T27(12.5,-1.5) T28(13.5,-1.5) U1(-13.5,-2.5) U2(-12.5,-2.5) U3(-11.5,-2.5) U4(-10.5,-2.5) U5(-9.5,-2.5) U6(-8.5,-2.5) U7(-7.5,-2.5) U8(-6.5,-2.5) U9(-5.5,-2.5) U10(-4.5,-2.5) U11(-3.5,-2.5) U12(-2.5,-2.5) U13(-1.5,-2.5) U14(-0.5,-2.5) U15(0.5,-2.5) U16(1.5,-2.5) U17(2.5,-2.5) U18(3.5,-2.5) U19(4.5,-2.5) U20(5.5,-2.5) U21(6.5,-2.5) U22(7.5,-2.5) U23(8.5,-2.5) U24(9.5,-2.5) U25(10.5,-2.5) U26(11.5,-2.5) U27(12.5,-2.5) U28(13.5,-2.5) V1(-13.5,-3.5) V2(-12.5,-3.5) V3(-11.5,-3.5) V4(-10.5,-3.5) V5(-9.5,-3.5) V6(-8.5,-3.5) V7(-7.5,-3.5) V8(-6.5,-3.5) V9(-5.5,-3.5) V10(-4.5,-3.5) V11(-3.5,-3.5) V12(-2.5,-3.5) V13(-1.5,-3.5) V14(-0.5,-3.5) V15(0.5,-3.5) V16(1.5,-3.5) V17(2.5,-3.5) V18(3.5,-3.5) V19(4.5,-3.5) V20(5.5,-3.5) V21(6.5,-3.5) V22(7.5,-3.5) V23(8.5,-3.5) V24(9.5,-3.5) V25(10.5,-3.5) V26(11.5,-3.5) V27(12.5,-3.5) V28(13.5,-3.5) W1(-13.5,-4.5) W2(-12.5,-4.5) W3(-11.5,-4.5) W4(-10.5,-4.5) W5(-9.5,-4.5) W6(-8.5,-4.5) W7(-7.5,-4.5) W8(-6.5,-4.5) W9(-5.5,-4.5) W10(-4.5,-4.5) W11(-3.5,-4.5) W12(-2.5,-4.5) W13(-1.5,-4.5) W14(-0.5,-4.5) W15(0.5,-4.5) W16(1.5,-4.5) W17(2.5,-4.5) W18(3.5,-4.5) W19(4.5,-4.5) W20(5.5,-4.5) W21(6.5,-4.5) W22(7.5,-4.5) W23(8.5,-4.5) W24(9.5,-4.5) W25(10.5,-4.5) W26(11.5,-4.5) W27(12.5,-4.5) W28(13.5,-4.5) Y1(-13.5,-5.5) Y2(-12.5,-5.5) Y3(-11.5,-5.5) Y4(-10.5,-5.5) Y5(-9.5,-5.5) Y6(-8.5,-5.5) Y7(-7.5,-5.5) Y8(-6.5,-5.5) Y9(-5.5,-5.5) Y10(-4.5,-5.5) Y11(-3.5,-5.5) Y12(-2.5,-5.5) Y13(-1.5,-5.5) Y14(-0.5,-5.5) Y15(0.5,-5.5) Y16(1.5,-5.5) Y17(2.5,-5.5) Y18(3.5,-5.5) Y19(4.5,-5.5) Y20(5.5,-5.5) Y21(6.5,-5.5) Y22(7.5,-5.5) Y23(8.5,-5.5) Y24(9.5,-5.5) Y25(10.5,-5.5) Y26(11.5,-5.5) Y27(12.5,-5.5) Y28(13.5,-5.5)
Top Overlay:
  circle w0.25: c-15.15,13.5 r0.125
  region: -13.5,14.5 -14.5,13.5 -14.5,14.5
  lines w0.2: -14.5,13.5 -13.5,14.5 ; -14.5,-14.5 14.5,-14.5 14.5,14.5 -14.5,14.5 -14.5,-14.5
Mechanical 13:
  lines w0.1: -14.5,-14.5 14.5,-14.5 14.5,14.5 -14.5,14.5 -14.5,-14.5
Mechanical 15:
  lines w0.1: -0.5,0 0.5,0 ; 0,-0.5 0,0.5 ; -15.5,-15.5 15.5,-15.5 15.5,15.5 -15.5,15.5 -15.5,-15.5
3D body: height 0, standoff 0, extent -14.5,-14.5 14.5,14.5

## BGA100P28X28-780A [mm] "BGA, 780-Leads, Body 33x33mm, Pitch 1mm"
height 3.5
pads (780):
  round 0.5 smd: A2(-12.5,13.5) A3(-11.5,13.5) A4(-10.5,13.5) A5(-9.5,13.5) A6(-8.5,13.5) A7(-7.5,13.5) A8(-6.5,13.5) A9(-5.5,13.5) A10(-4.5,13.5) A11(-3.5,13.5) A12(-2.5,13.5) A13(-1.5,13.5) A14(-0.5,13.5) A15(0.5,13.5) A16(1.5,13.5) A17(2.5,13.5) A18(3.5,13.5) A19(4.5,13.5) A20(5.5,13.5) A21(6.5,13.5) A22(7.5,13.5) A23(8.5,13.5) A24(9.5,13.5) A25(10.5,13.5) A26(11.5,13.5) A27(12.5,13.5) AA1(-13.5,-6.5) AA2(-12.5,-6.5) AA3(-11.5,-6.5) AA4(-10.5,-6.5) AA5(-9.5,-6.5) AA6(-8.5,-6.5) AA7(-7.5,-6.5) AA8(-6.5,-6.5) AA9(-5.5,-6.5) AA10(-4.5,-6.5) AA11(-3.5,-6.5) AA12(-2.5,-6.5) AA13(-1.5,-6.5) AA14(-0.5,-6.5) AA15(0.5,-6.5) AA16(1.5,-6.5) AA17(2.5,-6.5) AA18(3.5,-6.5) AA19(4.5,-6.5) AA20(5.5,-6.5) AA21(6.5,-6.5) AA22(7.5,-6.5) AA23(8.5,-6.5) AA24(9.5,-6.5) AA25(10.5,-6.5) AA26(11.5,-6.5) AA27(12.5,-6.5) AA28(13.5,-6.5) AB1(-13.5,-7.5) AB2(-12.5,-7.5) AB3(-11.5,-7.5) AB4(-10.5,-7.5) AB5(-9.5,-7.5) AB6(-8.5,-7.5) AB7(-7.5,-7.5) AB8(-6.5,-7.5) AB9(-5.5,-7.5) AB10(-4.5,-7.5) AB11(-3.5,-7.5) AB12(-2.5,-7.5) AB13(-1.5,-7.5) AB14(-0.5,-7.5) AB15(0.5,-7.5) AB16(1.5,-7.5) AB17(2.5,-7.5) AB18(3.5,-7.5) AB19(4.5,-7.5) AB20(5.5,-7.5) AB21(6.5,-7.5) AB22(7.5,-7.5) AB23(8.5,-7.5) AB24(9.5,-7.5) AB25(10.5,-7.5) AB26(11.5,-7.5) AB27(12.5,-7.5) AB28(13.5,-7.5) AC1(-13.5,-8.5) AC2(-12.5,-8.5) AC3(-11.5,-8.5) AC4(-10.5,-8.5) AC5(-9.5,-8.5) AC6(-8.5,-8.5) AC7(-7.5,-8.5) AC8(-6.5,-8.5) AC9(-5.5,-8.5) AC10(-4.5,-8.5) AC11(-3.5,-8.5) AC12(-2.5,-8.5) AC13(-1.5,-8.5) AC14(-0.5,-8.5) AC15(0.5,-8.5) AC16(1.5,-8.5) AC17(2.5,-8.5) AC18(3.5,-8.5) AC19(4.5,-8.5) AC20(5.5,-8.5) AC21(6.5,-8.5) AC22(7.5,-8.5) AC23(8.5,-8.5) AC24(9.5,-8.5) AC25(10.5,-8.5) AC26(11.5,-8.5) AC27(12.5,-8.5) AC28(13.5,-8.5) AD1(-13.5,-9.5) AD2(-12.5,-9.5) AD3(-11.5,-9.5) AD4(-10.5,-9.5) AD5(-9.5,-9.5) AD6(-8.5,-9.5) AD7(-7.5,-9.5) AD8(-6.5,-9.5) AD9(-5.5,-9.5) AD10(-4.5,-9.5) AD11(-3.5,-9.5) AD12(-2.5,-9.5) AD13(-1.5,-9.5) AD14(-0.5,-9.5) AD15(0.5,-9.5) AD16(1.5,-9.5) AD17(2.5,-9.5) AD18(3.5,-9.5) AD19(4.5,-9.5) AD20(5.5,-9.5) AD21(6.5,-9.5) AD22(7.5,-9.5) AD23(8.5,-9.5) AD24(9.5,-9.5) AD25(10.5,-9.5) AD26(11.5,-9.5) AD27(12.5,-9.5) AD28(13.5,-9.5) AE1(-13.5,-10.5) AE2(-12.5,-10.5) AE3(-11.5,-10.5) AE4(-10.5,-10.5) AE5(-9.5,-10.5) AE6(-8.5,-10.5) AE7(-7.5,-10.5) AE8(-6.5,-10.5) AE9(-5.5,-10.5) AE10(-4.5,-10.5) AE11(-3.5,-10.5) AE12(-2.5,-10.5) AE13(-1.5,-10.5) AE14(-0.5,-10.5) AE15(0.5,-10.5) AE16(1.5,-10.5) AE17(2.5,-10.5) AE18(3.5,-10.5) AE19(4.5,-10.5) AE20(5.5,-10.5) AE21(6.5,-10.5) AE22(7.5,-10.5) AE23(8.5,-10.5) AE24(9.5,-10.5) AE25(10.5,-10.5) AE26(11.5,-10.5) AE27(12.5,-10.5) AE28(13.5,-10.5) AF1(-13.5,-11.5) AF2(-12.5,-11.5) AF3(-11.5,-11.5) AF4(-10.5,-11.5) AF5(-9.5,-11.5) AF6(-8.5,-11.5) AF7(-7.5,-11.5) AF8(-6.5,-11.5) AF9(-5.5,-11.5) AF10(-4.5,-11.5) AF11(-3.5,-11.5) AF12(-2.5,-11.5) AF13(-1.5,-11.5) AF14(-0.5,-11.5) AF15(0.5,-11.5) AF16(1.5,-11.5) AF17(2.5,-11.5) AF18(3.5,-11.5) AF19(4.5,-11.5) AF20(5.5,-11.5) AF21(6.5,-11.5) AF22(7.5,-11.5) AF23(8.5,-11.5) AF24(9.5,-11.5) AF25(10.5,-11.5) AF26(11.5,-11.5) AF27(12.5,-11.5) AF28(13.5,-11.5) AG1(-13.5,-12.5) AG2(-12.5,-12.5) AG3(-11.5,-12.5) AG4(-10.5,-12.5) AG5(-9.5,-12.5) AG6(-8.5,-12.5) AG7(-7.5,-12.5) AG8(-6.5,-12.5) AG9(-5.5,-12.5) AG10(-4.5,-12.5) AG11(-3.5,-12.5) AG12(-2.5,-12.5) AG13(-1.5,-12.5) AG14(-0.5,-12.5) AG15(0.5,-12.5) AG16(1.5,-12.5) AG17(2.5,-12.5) AG18(3.5,-12.5) AG19(4.5,-12.5) AG20(5.5,-12.5) AG21(6.5,-12.5) AG22(7.5,-12.5) AG23(8.5,-12.5) AG24(9.5,-12.5) AG25(10.5,-12.5) AG26(11.5,-12.5) AG27(12.5,-12.5) AG28(13.5,-12.5) AH2(-12.5,-13.5) AH3(-11.5,-13.5) AH4(-10.5,-13.5) AH5(-9.5,-13.5) AH6(-8.5,-13.5) AH7(-7.5,-13.5) AH8(-6.5,-13.5) AH9(-5.5,-13.5) AH10(-4.5,-13.5) AH11(-3.5,-13.5) AH12(-2.5,-13.5) AH13(-1.5,-13.5) AH14(-0.5,-13.5) AH15(0.5,-13.5) AH16(1.5,-13.5) AH17(2.5,-13.5) AH18(3.5,-13.5) AH19(4.5,-13.5) AH20(5.5,-13.5) AH21(6.5,-13.5) AH22(7.5,-13.5) AH23(8.5,-13.5) AH24(9.5,-13.5) AH25(10.5,-13.5) AH26(11.5,-13.5) AH27(12.5,-13.5) B1(-13.5,12.5) B2(-12.5,12.5) B3(-11.5,12.5) B4(-10.5,12.5) B5(-9.5,12.5) B6(-8.5,12.5) B7(-7.5,12.5) B8(-6.5,12.5) B9(-5.5,12.5) B10(-4.5,12.5) B11(-3.5,12.5) B12(-2.5,12.5) B13(-1.5,12.5) B14(-0.5,12.5) B15(0.5,12.5) B16(1.5,12.5) B17(2.5,12.5) B18(3.5,12.5) B19(4.5,12.5) B20(5.5,12.5) B21(6.5,12.5) B22(7.5,12.5) B23(8.5,12.5) B24(9.5,12.5) B25(10.5,12.5) B26(11.5,12.5) B27(12.5,12.5) B28(13.5,12.5) C1(-13.5,11.5) C2(-12.5,11.5) C3(-11.5,11.5) C4(-10.5,11.5) C5(-9.5,11.5) C6(-8.5,11.5) C7(-7.5,11.5) C8(-6.5,11.5) C9(-5.5,11.5) C10(-4.5,11.5) C11(-3.5,11.5) C12(-2.5,11.5) C13(-1.5,11.5) C14(-0.5,11.5) C15(0.5,11.5) C16(1.5,11.5) C17(2.5,11.5) C18(3.5,11.5) C19(4.5,11.5) C20(5.5,11.5) C21(6.5,11.5) C22(7.5,11.5) C23(8.5,11.5) C24(9.5,11.5) C25(10.5,11.5) C26(11.5,11.5) C27(12.5,11.5) C28(13.5,11.5) D1(-13.5,10.5) D2(-12.5,10.5) D3(-11.5,10.5) D4(-10.5,10.5) D5(-9.5,10.5) D6(-8.5,10.5) D7(-7.5,10.5) D8(-6.5,10.5) D9(-5.5,10.5) D10(-4.5,10.5) D11(-3.5,10.5) D12(-2.5,10.5) D13(-1.5,10.5) D14(-0.5,10.5) D15(0.5,10.5) D16(1.5,10.5) D17(2.5,10.5) D18(3.5,10.5) D19(4.5,10.5) D20(5.5,10.5) D21(6.5,10.5) D22(7.5,10.5) D23(8.5,10.5) D24(9.5,10.5) D25(10.5,10.5) D26(11.5,10.5) D27(12.5,10.5) D28(13.5,10.5) E1(-13.5,9.5) E2(-12.5,9.5) E3(-11.5,9.5) E4(-10.5,9.5) E5(-9.5,9.5) E6(-8.5,9.5) E7(-7.5,9.5) E8(-6.5,9.5) E9(-5.5,9.5) E10(-4.5,9.5) E11(-3.5,9.5) E12(-2.5,9.5) E13(-1.5,9.5) E14(-0.5,9.5) E15(0.5,9.5) E16(1.5,9.5) E17(2.5,9.5) E18(3.5,9.5) E19(4.5,9.5) E20(5.5,9.5) E21(6.5,9.5) E22(7.5,9.5) E23(8.5,9.5) E24(9.5,9.5) E25(10.5,9.5) E26(11.5,9.5) E27(12.5,9.5) E28(13.5,9.5) F1(-13.5,8.5) F2(-12.5,8.5) F3(-11.5,8.5) F4(-10.5,8.5) F5(-9.5,8.5) F6(-8.5,8.5) F7(-7.5,8.5) F8(-6.5,8.5) F9(-5.5,8.5) F10(-4.5,8.5) F11(-3.5,8.5) F12(-2.5,8.5) F13(-1.5,8.5) F14(-0.5,8.5) F15(0.5,8.5) F16(1.5,8.5) F17(2.5,8.5) F18(3.5,8.5) F19(4.5,8.5) F20(5.5,8.5) F21(6.5,8.5) F22(7.5,8.5) F23(8.5,8.5) F24(9.5,8.5) F25(10.5,8.5) F26(11.5,8.5) F27(12.5,8.5) F28(13.5,8.5) G1(-13.5,7.5) G2(-12.5,7.5) G3(-11.5,7.5) G4(-10.5,7.5) G5(-9.5,7.5) G6(-8.5,7.5) G7(-7.5,7.5) G8(-6.5,7.5) G9(-5.5,7.5) G10(-4.5,7.5) G11(-3.5,7.5) G12(-2.5,7.5) G13(-1.5,7.5) G14(-0.5,7.5) G15(0.5,7.5) G16(1.5,7.5) G17(2.5,7.5) G18(3.5,7.5) G19(4.5,7.5) G20(5.5,7.5) G21(6.5,7.5) G22(7.5,7.5) G23(8.5,7.5) G24(9.5,7.5) G25(10.5,7.5) G26(11.5,7.5) G27(12.5,7.5) G28(13.5,7.5) H1(-13.5,6.5) H2(-12.5,6.5) H3(-11.5,6.5) H4(-10.5,6.5) H5(-9.5,6.5) H6(-8.5,6.5) H7(-7.5,6.5) H8(-6.5,6.5) H9(-5.5,6.5) H10(-4.5,6.5) H11(-3.5,6.5) H12(-2.5,6.5) H13(-1.5,6.5) H14(-0.5,6.5) H15(0.5,6.5) H16(1.5,6.5) H17(2.5,6.5) H18(3.5,6.5) H19(4.5,6.5) H20(5.5,6.5) H21(6.5,6.5) H22(7.5,6.5) H23(8.5,6.5) H24(9.5,6.5) H25(10.5,6.5) H26(11.5,6.5) H27(12.5,6.5) H28(13.5,6.5) J1(-13.5,5.5) J2(-12.5,5.5) J3(-11.5,5.5) J4(-10.5,5.5) J5(-9.5,5.5) J6(-8.5,5.5) J7(-7.5,5.5) J8(-6.5,5.5) J9(-5.5,5.5) J10(-4.5,5.5) J11(-3.5,5.5) J12(-2.5,5.5) J13(-1.5,5.5) J14(-0.5,5.5) J15(0.5,5.5) J16(1.5,5.5) J17(2.5,5.5) J18(3.5,5.5) J19(4.5,5.5) J20(5.5,5.5) J21(6.5,5.5) J22(7.5,5.5) J23(8.5,5.5) J24(9.5,5.5) J25(10.5,5.5) J26(11.5,5.5) J27(12.5,5.5) J28(13.5,5.5) K1(-13.5,4.5) K2(-12.5,4.5) K3(-11.5,4.5) K4(-10.5,4.5) K5(-9.5,4.5) K6(-8.5,4.5) K7(-7.5,4.5) K8(-6.5,4.5) K9(-5.5,4.5) K10(-4.5,4.5) K11(-3.5,4.5) K12(-2.5,4.5) K13(-1.5,4.5) K14(-0.5,4.5) K15(0.5,4.5) K16(1.5,4.5) K17(2.5,4.5) K18(3.5,4.5) K19(4.5,4.5) K20(5.5,4.5) K21(6.5,4.5) K22(7.5,4.5) K23(8.5,4.5) K24(9.5,4.5) K25(10.5,4.5) K26(11.5,4.5) K27(12.5,4.5) K28(13.5,4.5) L1(-13.5,3.5) L2(-12.5,3.5) L3(-11.5,3.5) L4(-10.5,3.5) L5(-9.5,3.5) L6(-8.5,3.5) L7(-7.5,3.5) L8(-6.5,3.5) L9(-5.5,3.5) L10(-4.5,3.5) L11(-3.5,3.5) L12(-2.5,3.5) L13(-1.5,3.5) L14(-0.5,3.5) L15(0.5,3.5) L16(1.5,3.5) L17(2.5,3.5) L18(3.5,3.5) L19(4.5,3.5) L20(5.5,3.5) L21(6.5,3.5) L22(7.5,3.5) L23(8.5,3.5) L24(9.5,3.5) L25(10.5,3.5) L26(11.5,3.5) L27(12.5,3.5) L28(13.5,3.5) M1(-13.5,2.5) M2(-12.5,2.5) M3(-11.5,2.5) M4(-10.5,2.5) M5(-9.5,2.5) M6(-8.5,2.5) M7(-7.5,2.5) M8(-6.5,2.5) M9(-5.5,2.5) M10(-4.5,2.5) M11(-3.5,2.5) M12(-2.5,2.5) M13(-1.5,2.5) M14(-0.5,2.5) M15(0.5,2.5) M16(1.5,2.5) M17(2.5,2.5) M18(3.5,2.5) M19(4.5,2.5) M20(5.5,2.5) M21(6.5,2.5) M22(7.5,2.5) M23(8.5,2.5) M24(9.5,2.5) M25(10.5,2.5) M26(11.5,2.5) M27(12.5,2.5) M28(13.5,2.5) N1(-13.5,1.5) N2(-12.5,1.5) N3(-11.5,1.5) N4(-10.5,1.5) N5(-9.5,1.5) N6(-8.5,1.5) N7(-7.5,1.5) N8(-6.5,1.5) N9(-5.5,1.5) N10(-4.5,1.5) N11(-3.5,1.5) N12(-2.5,1.5) N13(-1.5,1.5) N14(-0.5,1.5) N15(0.5,1.5) N16(1.5,1.5) N17(2.5,1.5) N18(3.5,1.5) N19(4.5,1.5) N20(5.5,1.5) N21(6.5,1.5) N22(7.5,1.5) N23(8.5,1.5) N24(9.5,1.5) N25(10.5,1.5) N26(11.5,1.5) N27(12.5,1.5) N28(13.5,1.5) P1(-13.5,0.5) P2(-12.5,0.5) P3(-11.5,0.5) P4(-10.5,0.5) P5(-9.5,0.5) P6(-8.5,0.5) P7(-7.5,0.5) P8(-6.5,0.5) P9(-5.5,0.5) P10(-4.5,0.5) P11(-3.5,0.5) P12(-2.5,0.5) P13(-1.5,0.5) P14(-0.5,0.5) P15(0.5,0.5) P16(1.5,0.5) P17(2.5,0.5) P18(3.5,0.5) P19(4.5,0.5) P20(5.5,0.5) P21(6.5,0.5) P22(7.5,0.5) P23(8.5,0.5) P24(9.5,0.5) P25(10.5,0.5) P26(11.5,0.5) P27(12.5,0.5) P28(13.5,0.5) R1(-13.5,-0.5) R2(-12.5,-0.5) R3(-11.5,-0.5) R4(-10.5,-0.5) R5(-9.5,-0.5) R6(-8.5,-0.5) R7(-7.5,-0.5) R8(-6.5,-0.5) R9(-5.5,-0.5) R10(-4.5,-0.5) R11(-3.5,-0.5) R12(-2.5,-0.5) R13(-1.5,-0.5) R14(-0.5,-0.5) R15(0.5,-0.5) R16(1.5,-0.5) R17(2.5,-0.5) R18(3.5,-0.5) R19(4.5,-0.5) R20(5.5,-0.5) R21(6.5,-0.5) R22(7.5,-0.5) R23(8.5,-0.5) R24(9.5,-0.5) R25(10.5,-0.5) R26(11.5,-0.5) R27(12.5,-0.5) R28(13.5,-0.5) T1(-13.5,-1.5) T2(-12.5,-1.5) T3(-11.5,-1.5) T4(-10.5,-1.5) T5(-9.5,-1.5) T6(-8.5,-1.5) T7(-7.5,-1.5) T8(-6.5,-1.5) T9(-5.5,-1.5) T10(-4.5,-1.5) T11(-3.5,-1.5) T12(-2.5,-1.5) T13(-1.5,-1.5) T14(-0.5,-1.5) T15(0.5,-1.5) T16(1.5,-1.5) T17(2.5,-1.5) T18(3.5,-1.5) T19(4.5,-1.5) T20(5.5,-1.5) T21(6.5,-1.5) T22(7.5,-1.5) T23(8.5,-1.5) T24(9.5,-1.5) T25(10.5,-1.5) T26(11.5,-1.5) T27(12.5,-1.5) T28(13.5,-1.5) U1(-13.5,-2.5) U2(-12.5,-2.5) U3(-11.5,-2.5) U4(-10.5,-2.5) U5(-9.5,-2.5) U6(-8.5,-2.5) U7(-7.5,-2.5) U8(-6.5,-2.5) U9(-5.5,-2.5) U10(-4.5,-2.5) U11(-3.5,-2.5) U12(-2.5,-2.5) U13(-1.5,-2.5) U14(-0.5,-2.5) U15(0.5,-2.5) U16(1.5,-2.5) U17(2.5,-2.5) U18(3.5,-2.5) U19(4.5,-2.5) U20(5.5,-2.5) U21(6.5,-2.5) U22(7.5,-2.5) U23(8.5,-2.5) U24(9.5,-2.5) U25(10.5,-2.5) U26(11.5,-2.5) U27(12.5,-2.5) U28(13.5,-2.5) V1(-13.5,-3.5) V2(-12.5,-3.5) V3(-11.5,-3.5) V4(-10.5,-3.5) V5(-9.5,-3.5) V6(-8.5,-3.5) V7(-7.5,-3.5) V8(-6.5,-3.5) V9(-5.5,-3.5) V10(-4.5,-3.5) V11(-3.5,-3.5) V12(-2.5,-3.5) V13(-1.5,-3.5) V14(-0.5,-3.5) V15(0.5,-3.5) V16(1.5,-3.5) V17(2.5,-3.5) V18(3.5,-3.5) V19(4.5,-3.5) V20(5.5,-3.5) V21(6.5,-3.5) V22(7.5,-3.5) V23(8.5,-3.5) V24(9.5,-3.5) V25(10.5,-3.5) V26(11.5,-3.5) V27(12.5,-3.5) V28(13.5,-3.5) W1(-13.5,-4.5) W2(-12.5,-4.5) W3(-11.5,-4.5) W4(-10.5,-4.5) W5(-9.5,-4.5) W6(-8.5,-4.5) W7(-7.5,-4.5) W8(-6.5,-4.5) W9(-5.5,-4.5) W10(-4.5,-4.5) W11(-3.5,-4.5) W12(-2.5,-4.5) W13(-1.5,-4.5) W14(-0.5,-4.5) W15(0.5,-4.5) W16(1.5,-4.5) W17(2.5,-4.5) W18(3.5,-4.5) W19(4.5,-4.5) W20(5.5,-4.5) W21(6.5,-4.5) W22(7.5,-4.5) W23(8.5,-4.5) W24(9.5,-4.5) W25(10.5,-4.5) W26(11.5,-4.5) W27(12.5,-4.5) W28(13.5,-4.5) Y1(-13.5,-5.5) Y2(-12.5,-5.5) Y3(-11.5,-5.5) Y4(-10.5,-5.5) Y5(-9.5,-5.5) Y6(-8.5,-5.5) Y7(-7.5,-5.5) Y8(-6.5,-5.5) Y9(-5.5,-5.5) Y10(-4.5,-5.5) Y11(-3.5,-5.5) Y12(-2.5,-5.5) Y13(-1.5,-5.5) Y14(-0.5,-5.5) Y15(0.5,-5.5) Y16(1.5,-5.5) Y17(2.5,-5.5) Y18(3.5,-5.5) Y19(4.5,-5.5) Y20(5.5,-5.5) Y21(6.5,-5.5) Y22(7.5,-5.5) Y23(8.5,-5.5) Y24(9.5,-5.5) Y25(10.5,-5.5) Y26(11.5,-5.5) Y27(12.5,-5.5) Y28(13.5,-5.5)
Top Overlay:
  circle w0.25: c-17.15,13.5 r0.125
  region: -15.5,16.5 -16.5,15.5 -16.5,16.5
  lines w0.2: -16.5,15.5 -15.5,16.5 ; -16.5,-16.5 16.5,-16.5 16.5,16.5 -16.5,16.5 -16.5,-16.5
Mechanical 13:
  lines w0.1: -16.5,-16.5 16.5,-16.5 16.5,16.5 -16.5,16.5 -16.5,-16.5
Mechanical 15:
  lines w0.1: -0.5,0 0.5,0 ; 0,-0.5 0,0.5 ; -17.5,-17.5 17.5,-17.5 17.5,17.5 -17.5,17.5 -17.5,-17.5
3D body: height 3.5, standoff 0, extent -16.5,-16.5 16.5,16.5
